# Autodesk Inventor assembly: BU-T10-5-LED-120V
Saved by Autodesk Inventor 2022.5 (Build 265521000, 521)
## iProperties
Created: 2024-07
Part Number: BU-T10-5-LED-120V
Document SubType Name: Assembly
Designer: AdminForWorker
Title: BU-T10-5-LED-120V
Author: AdminForWorker
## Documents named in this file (3)
- c:\worker\convert-fusion-r03-cosv3\tmp\job-1\63\temp\files\f0394d61-3fef-4993-9021-e7f535fc5560\BU-T10-5-LED-120V.iam
- c:\worker\convert-fusion-r03-cosv3\tmp\job-1\63\temp\files\f0394d61-3fef-4993-9021-e7f535fc5560\E26 Base.ipt
- c:\worker\convert-fusion-r03-cosv3\tmp\job-1\63\temp\files\f0394d61-3fef-4993-9021-e7f535fc5560\Part26.ipt
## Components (2 placed, 2 different names)
1. E26 Base:1
2. Part26
